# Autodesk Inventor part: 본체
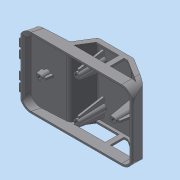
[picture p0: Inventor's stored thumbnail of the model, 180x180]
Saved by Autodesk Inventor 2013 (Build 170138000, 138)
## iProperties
Created: 2015-05
Part Number: 본체
Material: 일반
Document SubType Name: Modeling
Designer: Administrator
Density: 1 g/cm^3
Author: Administrator
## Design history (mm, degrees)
sketch "스케치1"
  geometry: L1 (0, 0)-(0, 1); L2 (120, 1)-(-1, 1); L3 (41, 12.075)-(52.826, 31); L4 (52.826, 31)-(91, 31); L5 (91, 31)-(117.378, 14.517); L6 (121, 1)-(120, 1); L7 (120, 1)-(120, 0); L8 (120, 0)-(0, 0); L9 (-1, 1)-(1.412, 10); L10 (1.412, 10)-(10, 10.45); L11 (30, 11.498)-(41, 12.075); L12 (55.597, 26)-(46.224, 11); L13 (80.224, 11)-(80.224, 26); L14 (80.224, 26)-(55.597, 26); L15 (85.571, 26)-(85.571, 11); L16 (85.571, 11)-(113.571, 11); L17 (113.571, 11)-(89.566, 26); L18 (89.566, 26)-(85.571, 26); L19 (46.224, 11)-(80.224, 11); L20 (121, 1)-(117.378, 14.517); L21 (10, 10.45)-(30, 11.498)
  constraints: 42 end point, 7 perpendicular, 6 parallel, 4 collinear, 2 vertical, 1 point on line
  dimensions: "d2" = 31 distance between parallel lines of L8 L4; "d3" = 30 horizontal distance of L4.end L6.start; "d10" = 11 horizontal distance of L10.end L2.end; "d12" = 122 distance of L6.start L2.end; "d13" = 20 horizontal distance of L11.start L10.end; "d20" = 125 deg angle of L3 L11; "d22" = 34 distance of L12.end L13.start; "d23" = 5 distance between parallel lines of L12 L3; "d25" = 15 distance of L13.start L13.end; "d26" = 5 distance between parallel lines of L5 L17; "d27" = 28 distance of L15.end L16.end; "d28" = 5 distance between parallel lines of L4 L18; "d29" = 42 horizontal distance of L3.start L2.end; "d30" = 9 vertical distance of L2.end L9.end; "d31" = 3 deg angle of L2 L11; "d32" = 1 distance between parallel lines of L8 L2; "d33" = 1 distance of L6.start L2.start; "d34" = 1 distance of L1.end L2.end; "d35" = 105 deg angle of L20 L2; "d45" = 105 deg angle of L9 L2
extrude "돌출1" new body sketch "스케치1" stored distance "d36" = 76; taper "d37" = 0 deg
fillet "모깎기1" dims "d57" = 3
fillet "모깎기2" dims "d58" = 12
sketch "스케치5"
  geometry: L1 (0, 0)-(-108.845, 0) reference; L2 (0, 0)-(0, 76) reference; L3 (-108.845, 76)-(0, 76) reference; L4 (1, 0)-(1, 76) reference; L5 (0, 76)-(1, 76) reference; L6 (1, 0)-(0, 0) reference; L7 (-11, 76)-(-137.694, 76); L8 (-137.694, 76)-(-137.694, 0); L9 (1, 64)-(1, 12); L10 (-137.694, 0)-(-11, 0); A1 r 12 centre (-11, 64) between (0, 59.204) and (-11, 76); A2 r 12 centre (-11, 12) between (-11, 0) and (0, 16.796); 3 further points; 1 other entity
  constraints: 8 end point, 6 point on circle, 6 point on line, 5 tangent, 2 centre point, 1 horizontal, 1 vertical, 1 other
  dimensions: "d60" = 24 diameter of A1; "d61" = 24 diameter of A2; "d62" = 138.69375 distance between parallel lines of L9 L8; "d63" = 76 distance of L7.end L8.end
extrude "돌출4" cut sketch "스케치5" stored distance "d64" = 26; taper "d65" = 0 deg
feature "쉘1" dims "d66" = 2
sketch "스케치2"
  geometry: L1 (-1, 1)-(1.412, 10) reference; L2 (1.412, 10)-(39.44, 11.993) reference; L3 (117.684, 13.376)-(121, 1) reference; L4 (121, 1)-(120, 1) reference; L5 (120, 1)-(120, 0) reference; L6 (120, 0)-(118, 0) reference; L7 (0, 0)-(0, 1) reference; L8 (0, 1)-(-1, 1) reference; L9 (11.556, 15.538)-(27.921, 16.396); L10 (27.921, 16.396)-(30, 11.498); L11 (11.556, 15.538)-(10, 10.45); L12 (41.828, 13.399)-(51.945, 29.59) reference; L13 (54.489, 31)-(90.14, 31) reference; L14 (91.73, 30.544)-(116.376, 15.143) reference; L15 (118, 0)-(118, 3) reference; L16 (118, 3)-(118.394, 3) reference; L17 (118.394, 3)-(115.752, 12.858) reference; L18 (115.316, 13.447)-(90.67, 28.848) reference; L19 (90.14, 29)-(54.489, 29) reference; L20 (53.641, 28.53)-(43.524, 12.339) reference; L21 (39.545, 9.996)-(2.967, 8.079) reference; L22 (2.967, 8.079)-(1.606, 3) reference; L23 (1.606, 3)-(2, 3) reference; L24 (2, 3)-(2, 0) reference; L25 (2, 0)-(0, 0) reference; A1 r 3 centre (39.283, 14.989) between (39.44, 11.993) and (41.828, 13.399) reference; A2 r 3 centre (54.489, 28) between (54.489, 31) and (51.945, 29.59) reference; A3 r 3 centre (90.14, 28) between (91.73, 30.544) and (90.14, 31) reference; A4 r 3 centre (114.786, 12.599) between (117.684, 13.376) and (116.376, 15.143) reference; A5 r 1 centre (114.786, 12.599) between (115.752, 12.858) and (115.316, 13.447) reference; A6 r 1 centre (90.14, 28) between (90.67, 28.848) and (90.14, 29) reference; A7 r 1 centre (54.489, 28) between (54.489, 29) and (53.641, 28.53) reference; A8 r 5 centre (39.283, 14.989) between (39.545, 9.996) and (43.524, 12.339) reference
  constraints: 6 end point, 2 point on line, 1 parallel
  dimensions: "d38" = 70 deg angle of L2 L11; "d39" = 70 deg angle of L2 L10; "d40" = 5 distance between parallel lines of L2 L9; "d41" = 11 horizontal distance of L11.end L1.start; "d42" = 20 horizontal distance of L10.end L11.end
extrude "돌출2" join sketch "스케치2" stored distance "d43" = 26; taper "d44" = 0 deg
node "작업 평면2"
  node "작업 평면1"
sketch "스케치3"
  geometry: A1 r 4 centre (0, -59) between (0, -55) and (0, -63); A2 r 4 centre (0, -48) between (0, -44) and (0, -52); A3 r 4 centre (0, -28) between (0, -24) and (0, -32); A4 r 4 centre (0, -17) between (0, -13) and (0, -21); 5 further points
  constraints: 8 point on circle, 4 centre point, 13 other
  dimensions: "d47" = 8 diameter of A1; "d48" = 8 diameter of A2; "d49" = 8 diameter of A3; "d50" = 8 diameter of A4; "d51" = 11 distance of A2.centre A1.centre; "d52" = 11 distance of A4.centre A3.centre; "d53" = 20 distance of A3.centre A2.centre; "d54" = 10 vertical distance of A3.centre point (1, -38)
extrude "돌출3" join sketch "스케치3" stored distance "d55" = 26; taper "d56" = 0 deg
extrude "돌출5" cut sketch "스케치1" stored distance "d67" = 26; taper "d68" = 0 deg
sketch "스케치6"
  geometry: L1 (11.155, 69.281)-(109, 69.281) reference; L2 (121, 5.281)-(121, 57.281) reference; C1 r 3 at (100, 31.281); 1 further point
  constraints: 1 centre point
  dimensions: "d69" = 6 diameter of C1; "d70" = 21 distance from line of C1.centre L2; "d71" = 38 distance from line of C1.centre L1
extrude "돌출6" join sketch "스케치6" stored distance "d72" = 2; taper "d73" = 2 deg
sketch "스케치10"
  geometry: L1 (96.93, 2)-(95, 2); L2 (95, 2)-(90.24, 28.995); L3 (103.07, 2)-(105, 2); L4 (105, 2)-(107.842, 18.118); L5 (39.545, 9.996)-(2.967, 8.079) reference; L6 (2.967, 8.079)-(1.606, 3) reference; L7 (1.606, 3)-(2, 3) reference; L8 (2, 3)-(2, 0) reference; L9 (2, 0)-(0, 0) reference; L10 (0, 0)-(0, 1) reference; L11 (0, 1)-(-1, 1) reference; L12 (-1, 1)-(1.412, 10) reference; L13 (1.412, 10)-(10, 10.45) reference; L14 (10, 10.45)-(11.556, 15.538) reference; L15 (11.556, 15.538)-(27.921, 16.396) reference; L16 (27.921, 16.396)-(30, 11.498) reference; L17 (30, 11.498)-(39.44, 11.993) reference; L18 (41.828, 13.399)-(51.945, 29.59) reference; L19 (54.489, 31)-(90.14, 31) reference; L20 (91.73, 30.544)-(116.376, 15.143) reference; L21 (117.684, 13.376)-(121, 1) reference; L22 (121, 1)-(120, 1) reference; L23 (120, 1)-(120, 0) reference; L24 (120, 0)-(118, 0) reference; L25 (118, 0)-(118, 3) reference; L26 (118, 3)-(118.394, 3) reference; L27 (118.394, 3)-(115.752, 12.858) reference; L28 (115.316, 13.447)-(103.723, 20.692) reference; L29 (103.723, 20.692)-(103, 0) reference; L30 (103, 0)-(97, 0) reference; L31 (97, 0)-(96.111, 25.448) reference; L32 (96.111, 25.448)-(90.67, 28.848) reference; L33 (90.14, 29)-(54.489, 29) reference; L34 (53.641, 28.53)-(43.524, 12.339) reference; L35 (100, 0.999)-(100, 23.47); L36 (109, 0)-(11.155, 0) reference; A1 r 3 centre (39.283, 14.989) between (39.44, 11.993) and (41.828, 13.399) reference; A2 r 3 centre (54.489, 28) between (54.489, 31) and (51.945, 29.59) reference; A3 r 3 centre (90.14, 28) between (91.73, 30.544) and (90.14, 31) reference; A4 r 3 centre (114.786, 12.599) between (117.684, 13.376) and (116.376, 15.143) reference; A5 r 1 centre (114.786, 12.599) between (115.752, 12.858) and (115.316, 13.447) reference; A6 r 1 centre (90.14, 28) between (90.67, 28.848) and (90.14, 29) reference; A7 r 1 centre (54.489, 28) between (54.489, 29) and (53.641, 28.53) reference; A8 r 5 centre (39.283, 14.989) between (39.545, 9.996) and (43.524, 12.339) reference
  constraints: 10 end point, 3 point on line, 1 collinear, 1 horizontal, 1 point on circle, 1 vertical
  dimensions: "d81" = 3 horizontal distance of L30.end L35.start; "d83" = 10 deg angle of L2 L35; "d84" = 10 deg angle of L4 L35; "d85" = 5 horizontal distance of L1.end L35.start; "d86" = 5 horizontal distance of L3.end L35.start; "d87" = 2 distance between parallel lines of L30 L1; "d88" = 2 distance between parallel lines of L36 L3
extrude "돌출8" join sketch "스케치10" stored distance "d89" = 2; taper "d90" = 0 deg
sketch "스케치11"
  geometry: C1 r 3 at (20, 31.281); C2 r 3 at (60, 9.281); C3 r 3 at (60, 53.281); C4 r 3 at (100, 31.281) reference; 1 further point
  constraints: 3 centre point, 1 horizontal alignment, 1 vertical alignment
  dimensions: "d92" = 6 diameter of C1; "d93" = 6 diameter of C2; "d94" = 6 diameter of C3; "d95" = 80 distance of C1.centre C4.centre; "d96" = 40 horizontal distance of C3.centre C4.centre; "d97" = 22 vertical distance of C2.centre C4.centre; "d98" = 22 vertical distance of C3.centre C4.centre
extrude "돌출9" join sketch "스케치11" stored distance "d99" = 2; taper "d100" = 2 deg
node "작업 평면5"
sketch "스케치12"
  geometry: L1 (-10, -76)-(-10, -74) reference; L2 (-10, -74)-(1, -74) reference; L3 (1, -74)-(1, -76) reference; L4 (1, -76)-(-10, -76) reference; L5 (-10, -2)-(-10, 0) reference; L6 (-10, 0)-(1, 0) reference; L7 (1, 0)-(1, -2) reference; L8 (1, -2)-(-10, -2) reference; L9 (-25, 0)-(-25, -2) reference; L10 (-25, -2)-(-28, -2) reference; L11 (-28, -2)-(-28, -11.987) reference; L12 (1, -13)-(1, -19) reference; L13 (-28, -20.013)-(-28, -55.987) reference; L14 (1, -57)-(1, -63) reference; L15 (-28, -64.013)-(-28, -74) reference; L16 (-28, -74)-(-25, -74) reference; L17 (-25, -74)-(-25, -76) reference; L18 (-25, -76)-(-30, -76) reference; L19 (-30, -76)-(-30, 0) reference; L20 (-30, 0)-(-25, 0) reference; L21 (-28, -69.761)-(-1, -65); L22 (-1, -65)-(-1, -61.021); L23 (-1, -61.021)-(-1, -55); L24 (-1, -55)-(-28, -50.239); L25 (-28, -25.761)-(-1, -21); L26 (-1, -21)-(-1, -11); L27 (-1, -11)-(-28, -6.239); L28 (1, -60)-(-23.647, -60); L29 (1, -16)-(-26.309, -16); L30 (-28, -11.987)-(1, -13) reference; L31 (1, -19)-(-28, -20.013) reference; L32 (-28, -55.987)-(1, -57) reference; L33 (1, -63)-(-28, -64.013) reference; 1 further point
  constraints: 18 end point, 4 point on line, 3 collinear, 2 midpoint, 2 parallel, 1 horizontal, 1 perpendicular
  dimensions: "d101" = 2 distance between parallel lines of L14 L22; "d105" = 10 deg angle of L29 L25; "d106" = 10 deg angle of L29 L27; "d107" = 10 deg angle of L28 L24; "d108" = 10 deg angle of L21 L28 (derived); "d109" = 10 distance of L26.end L25.end; "d110" = 5 vertical distance of L29.start L26.end; "d111" = 5 vertical distance of L28.start L23.end; "d112" = 10 distance of L21.end L23.end
extrude "돌출10" join sketch "스케치12" stored distance "d113" = 2; taper "d114" = 0 deg
sketch "스케치13"
  geometry: L1 (0, 1)-(-1, 1) reference; L2 (-1, 1)-(1.412, 10) reference; L3 (1.412, 10)-(10, 10.45) reference; L4 (10, 10.45)-(11.556, 15.538) reference; L5 (11.556, 15.538)-(27.921, 16.396) reference; L6 (27.921, 16.396)-(30, 11.498) reference; L7 (30, 11.498)-(39.44, 11.993) reference; L8 (41.828, 13.399)-(51.945, 29.59) reference; L9 (54.489, 31)-(90.14, 31) reference; L10 (91.73, 30.544)-(116.376, 15.143) reference; L11 (117.684, 13.376)-(121, 1) reference; L12 (121, 1)-(120, 1) reference; L13 (120, 1)-(120, 0) reference; L14 (120, 0)-(118, 0) reference; L15 (118, 0)-(118, 3) reference; L16 (118, 3)-(118.394, 3) reference; L17 (118.394, 3)-(115.752, 12.858) reference; L18 (115.316, 13.447)-(107.842, 18.118) reference; L19 (107.842, 18.118)-(105, 2) reference; L20 (105, 2)-(103.07, 2) reference; L21 (103.07, 2)-(103, 0) reference; L22 (103, 0)-(97, 0) reference; L23 (97, 0)-(96.93, 2) reference; L24 (96.111, 25.448)-(96.93, 2) reference; L25 (0, 0)-(0, 1) reference; L26 (2, 0)-(0, 0) reference; L27 (2, 3)-(2, 0) reference; L28 (1.606, 3)-(2, 3) reference; L29 (2.967, 8.079)-(1.606, 3) reference; L30 (16.693, 8.798)-(2.967, 8.079) reference; L31 (17, 0)-(16.693, 8.798) reference; L32 (23, 0)-(17, 0) reference; L33 (23.319, 9.145)-(23, 0) reference; L34 (39.545, 9.996)-(23.319, 9.145) reference; L35 (53.641, 28.53)-(43.524, 12.339) reference; L36 (90.14, 29)-(54.489, 29) reference; L37 (95, 2)-(90.24, 28.995) reference; L38 (96.93, 2)-(95, 2) reference; L39 (103.07, 2)-(103.723, 20.692) reference; L40 (13.828, 8.648)-(15, 2); L41 (15, 2)-(25, 2); L42 (20, 0)-(20, 8.438); L43 (25, 2)-(26.287, 9.301); A1 r 3 centre (39.283, 14.989) between (39.44, 11.993) and (41.828, 13.399) reference; A2 r 3 centre (54.489, 28) between (54.489, 31) and (51.945, 29.59) reference; A3 r 3 centre (90.14, 28) between (91.73, 30.544) and (90.14, 31) reference; A4 r 3 centre (114.786, 12.599) between (117.684, 13.376) and (116.376, 15.143) reference; A5 r 1 centre (114.786, 12.599) between (115.752, 12.858) and (115.316, 13.447) reference; A6 r 5 centre (39.283, 14.989) between (39.545, 9.996) and (43.524, 12.339) reference; A7 r 1 centre (54.489, 28) between (54.489, 29) and (53.641, 28.53) reference; A8 r 1 centre (90.14, 28) between (90.24, 28.995) and (90.14, 29) reference
  constraints: 8 end point, 2 point on line, 1 collinear, 1 midpoint, 1 perpendicular
  dimensions: "d115" = 2 distance between parallel lines of L32 L41; "d117" = 10 deg angle of L40 L42; "d119" = 10 distance of L41.end L40.end; "d120" = 5 horizontal distance of L41.end L42.start; "d121" = 10 deg angle of L43 L42
extrude "돌출11" join sketch "스케치13" stored distance "d122" = 2; taper "d123" = 0 deg
sketch "스케치14"
  geometry: L1 (39, 19)-(39, 19.172) reference; L2 (41, 19)-(39, 19) reference; L3 (41, 19.172)-(41, 19) reference; L4 (41, 25)-(41, 24.828) reference; L5 (41, 25)-(39, 25) reference; L6 (39, 24.828)-(39, 25) reference; L7 (83, -1)-(82.828, -1) reference; L8 (83, -1)-(83, 1) reference; L9 (82.828, 1)-(83, 1) reference; L10 (77, 1)-(77.172, 1) reference; L11 (77, -1)-(77, 1) reference; L12 (77.172, -1)-(77, -1) reference; L13 (39, -25)-(39, -24.828) reference; L14 (41, -25)-(39, -25) reference; L15 (41, -24.828)-(41, -25) reference; L16 (41, -19)-(41, -19.172) reference; L17 (41, -19)-(39, -19) reference; L18 (39, -19.172)-(39, -19) reference; C1 r 3 at (0, 0) reference; A1 r 3 centre (40, 22) between (39, 24.828) and (39, 19.172) reference; A2 r 3 centre (40, 22) between (41, 19.172) and (41, 24.828) reference; A3 r 3 centre (80, 0) between (77.172, -1) and (82.828, -1) reference; A4 r 3 centre (80, 0) between (82.828, 1) and (77.172, 1) reference; A5 r 3 centre (40, -22) between (39, -19.172) and (39, -24.828) reference; A6 r 3 centre (40, -22) between (41, -24.828) and (41, -19.172) reference; 1 further point
hole "구멍1" sketch "스케치14" at (0, 0), (40, 22), (80, 0), (40, -22) diameter "d124" = 3.242; stored, may be unused: countersink angle "d128" = 90 deg, drill point angle "d130" = 118 deg; dims "d125" = 9, "d126" = 4, "d127" = 2, "d129" = 11
sketch "스케치15"
  geometry: L1 (66.511, -12)-(66.511, -64) reference; 2 further points
  constraints: 1 horizontal alignment, 1 other
  dimensions: "d131" = 50 distance from line of point (16.511, -38) L1
feature "엠보싱1" sketch "스케치15" dims "d2" = 31, "d3" = 30, "d10" = 11, "d12" = 122, "d13" = 20, "d20" = 125 deg, "d22" = 34, "d23" = 5, "d25" = 15, "d26" = 5, "d27" = 28, "d28" = 5, "d29" = 42, "d30" = 9, "d31" = 3 deg, "d32" = 1, "d33" = 1, "d34" = 1, "d35" = 105 deg, "d45" = 105 deg, "d132" = 0.5, "d133" = 0
fillet "모깎기3" dims "d134" = 3
fillet "모깎기4" dims "d135" = 3
node "솔리드1"
node "투영된 루프1"
node "투영된 루프2"
node "투영된 루프3"
node "투영된 루프4"
node "절단 모서리 투영1"
node "절단 모서리 투영2"
node "절단 모서리 투영3"
node "절단 모서리 투영4"
other parameters: "d9" = 5, "d11" = 3 deg, "d14" = 110 deg, "d15" = 125 deg, "d46" = -2, "d91" = -63
